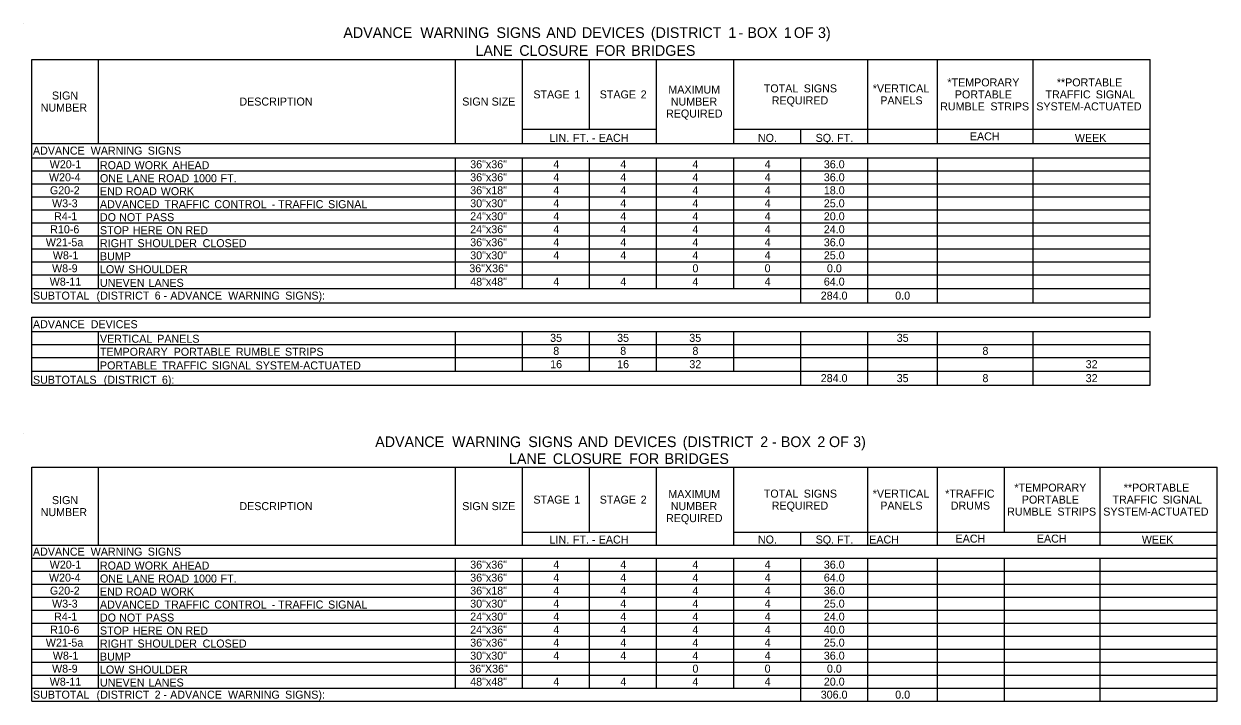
# Model space of a CAD drawing. Extents: x 542596 to 1930787, y -1948294 to 596640.
# Drawn here: x 542596 to 543491, y -1946520 to -1946012 of the extents above; entities that cross this region are included whole.
import ezdxf

# ---------------------------------------------------------------- set-up
doc = ezdxf.new("R2010")
doc.units = 0
doc.layers.add('Default', color=7, linetype='Continuous')

msp = doc.modelspace()

# ---------------------------------------------------------------- linework, layer by layer
at = {"layer": 'Default'}
for p, q in [((542596.4, -1946012.3), (542596.4, -1946012.3)), ((542602.25, -1946039.11), (543440.75, -1946039.11)), ((542602.25, -1946221.43), (542602.25, -1946039.11)), ((542602.25, -1946221.43), (542602.25, -1946039.11)), ((542652.46, -1946102), (542652.46, -1946039.11)), ((542920.1, -1946102), (542920.1, -1946039.11)), ((542970.31, -1946102), (542970.31, -1946039.11)), ((543020.52, -1946091.27), (543020.52, -1946039.11)), ((543070.73, -1946102), (543070.73, -1946039.11)), ((543128.75, -1946102), (543128.75, -1946039.11)), ((543229.17, -1946102), (543229.17, -1946039.11)), ((543281.33, -1946102), (543281.33, -1946039.11)), ((543353, -1946102), (543353, -1946039.11)), ((543440.75, -1946232.16), (543440.75, -1946039.11)), ((542970.31, -1946091.27), (543070.73, -1946091.27)), ((543070.73, -1946102), (543070.73, -1946091.27)), ((543128.75, -1946091.27), (543440.75, -1946091.27)), ((543178.96, -1946102), (543178.96, -1946091.27)), ((543229.17, -1946102), (543229.17, -1946091.27)), ((543281.33, -1946102), (543281.33, -1946091.27)), ((543353, -1946102), (543353, -1946091.27)), ((542602.25, -1946102), (543440.75, -1946102)), ((543070.73, -1946102), (543229.17, -1946102)), ((543229.17, -1946102), (543281.33, -1946102)), ((543281.33, -1946102), (543440.75, -1946102)), ((542602.25, -1946112.72), (543440.75, -1946112.72)), ((542652.46, -1946210.71), (542652.46, -1946112.72)), ((542652.46, -1946210.71), (542652.46, -1946112.72)), ((542920.1, -1946210.71), (542920.1, -1946112.72)), ((542920.1, -1946210.71), (542920.1, -1946112.72)), ((542970.31, -1946210.71), (542970.31, -1946112.72)), ((542970.31, -1946210.71), (542970.31, -1946112.72)), ((543020.52, -1946200.47), (543020.52, -1946112.72)), ((543020.52, -1946210.71), (543020.52, -1946112.72)), ((543070.73, -1946210.71), (543070.73, -1946112.72)), ((543070.73, -1946210.71), (543070.73, -1946112.72)), ((543128.75, -1946210.71), (543128.75, -1946112.72)), ((543178.96, -1946210.71), (543178.96, -1946112.72)), ((543178.96, -1946221.43), (543178.96, -1946112.72)), ((543229.17, -1946200.47), (543229.17, -1946112.72)), ((543229.17, -1946221.43), (543229.17, -1946112.72)), ((543281.33, -1946161.47), (543281.33, -1946112.72)), ((543281.33, -1946221.43), (543281.33, -1946112.72)), ((543353, -1946221.43), (543353, -1946112.72)), ((542602.25, -1946122.47), (543440.75, -1946122.47)), ((542602.25, -1946132.22), (543440.75, -1946132.22)), ((542602.25, -1946141.97), (543440.75, -1946141.97)), ((542602.25, -1946151.72), (543440.75, -1946151.72)), ((542602.25, -1946161.47), (543440.75, -1946161.47)), ((542602.25, -1946171.22), (543440.75, -1946171.22)), ((543281.33, -1946221.43), (543281.33, -1946171.22)), ((542602.25, -1946180.97), (543440.75, -1946180.97)), ((542602.25, -1946190.72), (543440.75, -1946190.72)), ((542602.25, -1946200.47), (543440.75, -1946200.47)), ((542602.25, -1946210.71), (543440.75, -1946210.71)), ((543178.96, -1946210.71), (543440.75, -1946210.71)), ((543353, -1946221.43), (543353, -1946210.71)), ((542602.25, -1946221.43), (543440.75, -1946221.43)), ((543353, -1946221.43), (543440.75, -1946221.43)), ((542602.25, -1946232.16), (543440.75, -1946232.16)), ((542602.25, -1946283.35), (542602.25, -1946232.16)), ((542602.25, -1946283.35), (542602.25, -1946232.16)), ((542652.46, -1946232.16), (543353, -1946232.16)), ((543353, -1946232.16), (543440.75, -1946232.16)), ((542602.25, -1946242.88), (543440.75, -1946242.88)), ((542652.46, -1946272.62), (542652.46, -1946242.88)), ((542652.46, -1946272.62), (542652.46, -1946242.88)), ((542920.1, -1946272.62), (542920.1, -1946242.88)), ((542920.1, -1946272.62), (542920.1, -1946242.88)), ((542970.31, -1946272.62), (542970.31, -1946242.88)), ((542970.31, -1946272.62), (542970.31, -1946242.88)), ((543020.52, -1946272.62), (543020.52, -1946242.88)), ((543020.52, -1946272.62), (543020.52, -1946242.88)), ((543070.73, -1946272.62), (543070.73, -1946242.88)), ((543070.73, -1946272.62), (543070.73, -1946242.88)), ((543128.75, -1946272.62), (543128.75, -1946242.88)), ((543178.96, -1946272.62), (543178.96, -1946242.88)), ((543178.96, -1946283.35), (543178.96, -1946242.88)), ((543229.17, -1946283.35), (543229.17, -1946242.88)), ((543229.17, -1946283.35), (543229.17, -1946242.88)), ((543281.33, -1946283.35), (543281.33, -1946242.88)), ((543281.33, -1946283.35), (543281.33, -1946242.88)), ((543353, -1946283.35), (543353, -1946242.88)), ((543440.75, -1946283.35), (543440.75, -1946242.88)), ((542602.25, -1946252.63), (543440.75, -1946252.63)), ((543353, -1946262.38), (543353, -1946252.63)), ((542602.25, -1946262.38), (543440.75, -1946262.38)), ((542602.25, -1946272.62), (543440.75, -1946272.62)), ((542602.25, -1946272.62), (543440.75, -1946272.62)), ((543353, -1946283.35), (543353, -1946272.62)), ((542602.25, -1946283.35), (543440.75, -1946283.35)), ((542596.4, -1946319.34), (542596.4, -1946319.34)), ((542602.25, -1946344.69), (543490.96, -1946344.69)), ((542602.25, -1946520.19), (542602.25, -1946344.69)), ((542602.25, -1946520.19), (542602.25, -1946344.69)), ((542652.46, -1946403.19), (542652.46, -1946344.69)), ((542920.1, -1946403.19), (542920.1, -1946344.69)), ((542970.31, -1946403.19), (542970.31, -1946344.69)), ((543020.52, -1946393.44), (543020.52, -1946344.69)), ((543070.73, -1946403.19), (543070.73, -1946344.69)), ((543128.75, -1946403.19), (543128.75, -1946344.69)), ((543229.17, -1946403.19), (543229.17, -1946344.69)), ((543281.33, -1946403.19), (543281.33, -1946344.69)), ((543331.55, -1946393.44), (543331.55, -1946344.69)), ((543403.21, -1946403.19), (543403.21, -1946344.69)), ((543490.96, -1946520.19), (543490.96, -1946344.69)), ((542970.31, -1946393.44), (543070.73, -1946393.44)), ((543070.73, -1946403.19), (543070.73, -1946393.44)), ((543128.75, -1946393.44), (543490.96, -1946393.44)), ((543178.96, -1946403.19), (543178.96, -1946393.44)), ((543281.33, -1946403.19), (543281.33, -1946393.44)), ((543403.21, -1946403.19), (543403.21, -1946393.44)), ((542602.25, -1946403.19), (543490.96, -1946403.19)), ((543070.73, -1946403.19), (543490.96, -1946403.19)), ((542602.25, -1946412.94), (543490.96, -1946412.94)), ((542652.46, -1946510.44), (542652.46, -1946412.94)), ((542652.46, -1946510.44), (542652.46, -1946412.94)), ((542920.1, -1946510.44), (542920.1, -1946412.94)), ((542920.1, -1946510.44), (542920.1, -1946412.94)), ((542970.31, -1946510.44), (542970.31, -1946412.94)), ((542970.31, -1946510.44), (542970.31, -1946412.94)), ((543020.52, -1946500.69), (543020.52, -1946412.94)), ((543020.52, -1946510.44), (543020.52, -1946412.94)), ((543070.73, -1946510.44), (543070.73, -1946412.94)), ((543070.73, -1946510.44), (543070.73, -1946412.94)), ((543128.75, -1946510.44), (543128.75, -1946412.94)), ((543178.96, -1946510.44), (543178.96, -1946412.94)), ((543178.96, -1946520.19), (543178.96, -1946412.94)), ((543229.17, -1946520.19), (543229.17, -1946412.94)), ((543229.17, -1946520.19), (543229.17, -1946412.94)), ((543281.33, -1946520.19), (543281.33, -1946412.94)), ((543281.33, -1946520.19), (543281.33, -1946412.94)), ((543331.55, -1946520.19), (543331.55, -1946412.94)), ((543331.55, -1946520.19), (543331.55, -1946412.94)), ((543403.21, -1946520.19), (543403.21, -1946412.94)), ((542602.25, -1946422.69), (543490.96, -1946422.69)), ((542602.25, -1946432.44), (543490.96, -1946432.44)), ((542602.25, -1946442.19), (543490.96, -1946442.19)), ((542602.25, -1946451.94), (543490.96, -1946451.94)), ((542602.25, -1946461.69), (543490.96, -1946461.69)), ((542602.25, -1946471.44), (543490.96, -1946471.44)), ((542602.25, -1946481.19), (543490.96, -1946481.19)), ((542602.25, -1946490.94), (543490.96, -1946490.94)), ((542602.25, -1946500.69), (543490.96, -1946500.69)), ((542602.25, -1946510.44), (543490.96, -1946510.44)), ((542602.25, -1946510.44), (543178.96, -1946510.44)), ((543281.33, -1946510.44), (543490.96, -1946510.44)), ((543403.21, -1946520.19), (543403.21, -1946510.44)), ((542602.25, -1946520.19), (543490.96, -1946520.19))]:
    msp.add_line(p, q, dxfattribs=at)

# ---------------------------------------------------------------- texts
for s, height, p in [('ADVANCE', 8, (542835.92, -1946022.88)), (' WARNING', 8, (542890.64, -1946022.88)), (' SIGNS', 8, (542947.71, -1946022.88)), (' AND', 8, (542985.05, -1946022.88)), (' DEVICES', 8, (543011.82, -1946022.88)), (' (DISTRICT', 8, (543063.45, -1946022.88)), (' 1', 8, (543121.59, -1946022.88)), (' -', 8, (543129.09, -1946022.88)), (' BOX', 8, (543135.84, -1946022.88)), (' 1', 8, (543163.15, -1946022.88)), (' OF', 8, (543170.66, -1946022.88)), (' 3)', 8, (543188.77, -1946022.88)), ('LANE', 8, (542934.96, -1946036.28)), (' CLOSURE', 8, (542964.84, -1946036.28)), (' FOR', 8, (543022.05, -1946036.28)), (' BRIDGES', 8, (543048.69, -1946036.28)), ('TOTAL', 6, (543151.11, -1946063.69)), (' SIGNS', 6, (543178.8, -1946063.69)), ('*VERTICAL', 6, (543232.79, -1946063.69)), ('*TEMPORARY', 6, (543288.74, -1946059.19)), ('**PORTABLE', 6, (543370.76, -1946059.19)), ('SIGN', 6, (542617.44, -1946069.05)), ('STAGE', 6, (542978.37, -1946068.19)), (' 1', 6, (543006.84, -1946068.19)), ('STAGE', 6, (543028.11, -1946068.19)), (' 2', 6, (543056.58, -1946068.19)), ('MAXIMUM', 6, (543079.55, -1946064.55)), ('REQUIRED', 6, (543157.04, -1946072.69)), ('PANELS', 6, (543238.45, -1946072.69)), ('PORTABLE', 6, (543294.32, -1946068.19)), ('TRAFFIC', 6, (543362.28, -1946068.19)), (' SIGNAL', 6, (543397.71, -1946068.19)), ('NUMBER', 6, (542608.98, -1946078.05)), ('DESCRIPTION', 6, (542757.97, -1946073.55)), ('SIGN', 6, (542925.02, -1946073.55)), (' SIZE', 6, (542944.84, -1946073.55)), ('NUMBER', 6, (543081.36, -1946073.55)), ('RUMBLE', 6, (543283.34, -1946077.19)), (' STRIPS', 6, (543318.79, -1946077.19)), ('SYSTEM-ACTUATED', 6, (543355.39, -1946077.19)), ('REQUIRED', 6, (543077.82, -1946082.55)), ('EACH', 6, (543305.61, -1946099.63)), ('LIN.', 6, (542990.48, -1946100.8)), (' FT.', 6, (543005.74, -1946100.8)), (' -', 6, (543020.06, -1946100.8)), (' EACH', 6, (543025.12, -1946100.8)), ('NO.', 6, (543146.69, -1946100.8)), ('SQ.', 6, (543189.97, -1946100.8)), (' FT.', 6, (543203.84, -1946100.8)), ('WEEK', 6, (543384.3, -1946100.8)), ('ADVANCE', 6, (542603.22, -1946110.36)), (' WARNING', 6, (542644.27, -1946110.36)), (' SIGNS', 6, (542687.07, -1946110.36)), ('W20-1', 6, (542615.78, -1946120.6)), ('ROAD', 6, (542653.43, -1946121.27)), (' WORK', 6, (542677.21, -1946121.27)), (' AHEAD', 6, (542705.6, -1946121.27)), ('36"x36"', 6, (542931.01, -1946120.6)), ('4', 6, (542993.29, -1946120.6)), ('4', 6, (543043.5, -1946120.6)), ('4', 6, (543097.61, -1946120.6)), ('4', 6, (543151.73, -1946120.6)), ('36.0', 6, (543196.11, -1946120.6)), ('W20-4', 6, (542615.22, -1946130.35)), ('ONE', 6, (542653.43, -1946131.02)), (' LANE', 6, (542671.16, -1946131.02)), (' ROAD', 6, (542694.94, -1946131.02)), (' 1000', 6, (542721.04, -1946131.02)), (' FT.', 6, (542741.61, -1946131.02)), ('36"x36"', 6, (542931.01, -1946130.35)), ('4', 6, (542993.29, -1946130.35)), ('4', 6, (543043.5, -1946130.35)), ('4', 6, (543097.61, -1946130.35)), ('4', 6, (543151.73, -1946130.35)), ('36.0', 6, (543196.11, -1946130.35)), ('G20-2', 6, (542615.93, -1946140.1)), ('END', 6, (542653.43, -1946140.77)), (' ROAD', 6, (542670.69, -1946140.77)), (' WORK', 6, (542696.79, -1946140.77)), ('36"x18"', 6, (542931.01, -1946140.1)), ('4', 6, (542993.29, -1946140.1)), ('4', 6, (543043.5, -1946140.1)), ('4', 6, (543097.61, -1946140.1)), ('4', 6, (543151.73, -1946140.1)), ('18.0', 6, (543196.11, -1946140.1)), ('W3-3', 6, (542617.53, -1946149.85)), ('ADVANCED', 6, (542653.43, -1946150.52)), (' TRAFFIC', 6, (542699.58, -1946150.52)), (' CONTROL', 6, (542736.97, -1946150.52)), (' TRAFFIC', 6, (542784.84, -1946150.52)), (' SIGNAL', 6, (542822.23, -1946150.52)), ('30"x30"', 6, (542931.01, -1946149.85)), ('4', 6, (542993.29, -1946149.85)), ('4', 6, (543043.5, -1946149.85)), ('4', 6, (543097.61, -1946149.85)), ('4', 6, (543151.73, -1946149.85)), ('25.0', 6, (543196.11, -1946149.85)), ('R4-1', 6, (542619.04, -1946159.6)), ('DO', 6, (542653.43, -1946160.27)), (' NOT', 6, (542665.64, -1946160.27)), (' PASS', 6, (542685.49, -1946160.27)), (' -', 6, (542779.99, -1946150.52)), ('24"x30"', 6, (542931.01, -1946159.6)), ('4', 6, (542993.29, -1946159.6)), ('4', 6, (543043.5, -1946159.6)), ('4', 6, (543097.61, -1946159.6)), ('4', 6, (543151.73, -1946159.6)), ('20.0', 6, (543196.11, -1946159.6)), ('R10-6', 6, (542616.13, -1946169.35)), ('STOP', 6, (542653.43, -1946170.02)), (' HERE', 6, (542675.9, -1946170.02)), (' ON', 6, (542701.07, -1946170.02)), (' RED', 6, (542715.29, -1946170.02)), ('24"x36"', 6, (542931.01, -1946169.35)), ('4', 6, (542993.29, -1946169.35)), ('4', 6, (543043.5, -1946169.35)), ('4', 6, (543097.61, -1946169.35)), ('4', 6, (543151.73, -1946169.35)), ('24.0', 6, (543196.11, -1946169.35)), ('W21-5a', 6, (542612.86, -1946179.1)), ('RIGHT', 6, (542653.43, -1946179.77)), (' SHOULDER', 6, (542679.35, -1946179.77)), (' CLOSED', 6, (542728.15, -1946179.77)), ('36"x36"', 6, (542931.01, -1946179.1)), ('4', 6, (542993.29, -1946179.1)), ('4', 6, (543043.5, -1946179.1)), ('4', 6, (543097.61, -1946179.1)), ('4', 6, (543151.73, -1946179.1)), ('36.0', 6, (543196.11, -1946179.1)), ('W8-1', 6, (542618.11, -1946188.85)), ('30"x30"', 6, (542931.01, -1946188.85)), ('4', 6, (542993.29, -1946188.85)), ('4', 6, (543043.5, -1946188.85)), ('4', 6, (543097.61, -1946188.85)), ('4', 6, (543151.73, -1946188.85)), ('25.0', 6, (543196.11, -1946188.85)), ('BUMP', 6, (542653.43, -1946189.52)), ('W8-9', 6, (542617.53, -1946198.6)), ('LOW', 6, (542653.43, -1946199.27)), (' SHOULDER', 6, (542672.43, -1946199.27)), ('36"X36"', 6, (542930.31, -1946198.6)), ('0', 6, (543097.61, -1946198.6)), ('0', 6, (543151.72, -1946198.6)), ('0.0', 6, (543198.44, -1946198.6)), ('W8-11', 6, (542615.78, -1946208.59)), ('UNEVEN', 6, (542653.43, -1946209.51)), (' LANES', 6, (542687.69, -1946209.51)), ('48"x48"', 6, (542931.01, -1946208.59)), ('4', 6, (542993.29, -1946208.59)), ('4', 6, (543043.5, -1946208.59)), ('4', 6, (543097.61, -1946208.59)), ('4', 6, (543151.73, -1946208.59)), ('64.0', 6, (543196.11, -1946208.59)), ('SUBTOTAL', 6, (542603.22, -1946219.07)), (' (DISTRICT', 6, (542648.62, -1946219.07)), (' 6', 6, (542692.22, -1946219.07)), (' -', 6, (542698.91, -1946219.07)), (' ADVANCE', 6, (542703.96, -1946219.07)), (' WARNING', 6, (542747.34, -1946219.07)), (' SIGNS):', 6, (542790.14, -1946219.07)), ('284.0', 6, (543193.79, -1946219.07)), ('0.0', 6, (543249.64, -1946219.07)), ('ADVANCE', 6, (542603.22, -1946240.52)), (' DEVICES', 6, (542644.27, -1946240.52)), ('VERTICAL', 6, (542653.43, -1946251.43)), (' PANELS', 6, (542694.14, -1946251.43)), ('35', 6, (542990.92, -1946250.76)), ('35', 6, (543041.14, -1946250.76)), ('35', 6, (543095.25, -1946250.76)), ('35', 6, (543250.76, -1946250.76)), ('8', 6, (542993.27, -1946260.51)), ('8', 6, (543043.48, -1946260.51)), ('8', 6, (543097.6, -1946260.51)), ('8', 6, (543315.02, -1946260.51)), ('TEMPORARY', 6, (542653.43, -1946261.18)), (' PORTABLE', 6, (542706.48, -1946261.18)), (' RUMBLE', 6, (542753.09, -1946261.18)), (' STRIPS', 6, (542789.91, -1946261.18)), ('PORTABLE', 6, (542653.43, -1946271.42)), (' TRAFFIC', 6, (542697.72, -1946271.42)), (' SIGNAL', 6, (542735.11, -1946271.42)), (' SYSTEM-ACTUATED', 6, (542767.89, -1946271.42)), ('16', 6, (542990.95, -1946270.5)), ('16', 6, (543041.16, -1946270.5)), ('32', 6, (543095.3, -1946270.5)), ('32', 6, (543392.43, -1946270.5)), ('SUBTOTALS', 6, (542603.22, -1946282.15)), (' (DISTRICT', 6, (542654.05, -1946282.15)), (' 6):', 6, (542697.65, -1946282.15)), ('284.0', 6, (543193.79, -1946280.98)), ('35', 6, (543250.72, -1946280.98)), ('8', 6, (543315.02, -1946280.98)), ('32', 6, (543392.42, -1946280.98)), ('ADVANCE', 8, (542859.77, -1946329.68)), (' WARNING', 8, (542914.5, -1946329.68)), (' SIGNS', 8, (542971.57, -1946329.68)), (' AND', 8, (543008.91, -1946329.68)), (' DEVICES', 8, (543035.68, -1946329.68)), (' (DISTRICT', 8, (543087.31, -1946329.68)), (' 2', 8, (543145.44, -1946329.68)), (' -', 8, (543154.2, -1946329.68)), (' BOX', 8, (543160.94, -1946329.68)), (' 2', 8, (543188.26, -1946329.68)), (' OF', 8, (543197.02, -1946329.68)), (' 3)', 8, (543215.13, -1946329.68)), ('LANE', 8, (542960.07, -1946342.35)), (' CLOSURE', 8, (542989.95, -1946342.35)), (' FOR', 8, (543047.15, -1946342.35)), (' BRIDGES', 8, (543073.8, -1946342.35)), ('MAXIMUM', 6, (543079.55, -1946367.94)), ('TOTAL', 6, (543151.11, -1946367.56)), (' SIGNS', 6, (543178.8, -1946367.56)), ('*VERTICAL', 6, (543232.79, -1946367.56)), ('*TRAFFIC', 6, (543287.1, -1946367.56)), ('*TEMPORARY', 6, (543338.96, -1946363.06)), ('**PORTABLE', 6, (543420.97, -1946363.06)), ('SIGN', 6, (542617.44, -1946372.44)), ('DESCRIPTION', 6, (542757.97, -1946376.94)), ('SIGN', 6, (542925.02, -1946376.94)), (' SIZE', 6, (542944.84, -1946376.94)), ('STAGE', 6, (542978.37, -1946372.06)), (' 1', 6, (543006.84, -1946372.06)), ('STAGE', 6, (543028.11, -1946372.06)), (' 2', 6, (543056.58, -1946372.06)), ('NUMBER', 6, (543081.36, -1946376.94)), ('REQUIRED', 6, (543157.04, -1946376.56)), ('PANELS', 6, (543238.45, -1946376.56)), ('DRUMS', 6, (543291.28, -1946376.56)), ('PORTABLE', 6, (543344.53, -1946372.06)), ('TRAFFIC', 6, (543412.5, -1946372.06)), (' SIGNAL', 6, (543447.92, -1946372.06)), ('NUMBER', 6, (542608.98, -1946381.44)), ('REQUIRED', 6, (543077.82, -1946385.94)), ('RUMBLE', 6, (543333.56, -1946381.06)), (' STRIPS', 6, (543369, -1946381.06)), ('SYSTEM-ACTUATED', 6, (543405.6, -1946381.06)), ('LIN.', 6, (542990.48, -1946401.99)), (' FT.', 6, (543005.74, -1946401.99)), (' EACH', 6, (543025.12, -1946401.99)), ('NO.', 6, (543146.69, -1946401.99)), ('SQ.', 6, (543189.97, -1946401.99)), (' FT.', 6, (543203.84, -1946401.99)), ('EACH', 6, (543230.15, -1946401.99)), ('EACH', 6, (543294.88, -1946401.31)), ('EACH', 6, (543355.82, -1946401.31)), ('WEEK', 6, (543434.52, -1946401.99)), ('ADVANCE', 6, (542603.22, -1946411.06)), (' WARNING', 6, (542644.27, -1946411.06)), (' SIGNS', 6, (542687.07, -1946411.06)), (' -', 6, (543020.06, -1946401.99)), ('W20-1', 6, (542615.78, -1946420.81)), ('ROAD', 6, (542653.43, -1946421.49)), (' WORK', 6, (542677.21, -1946421.49)), (' AHEAD', 6, (542705.6, -1946421.49)), ('36"x36"', 6, (542931.01, -1946420.81)), ('4', 6, (542993.29, -1946420.81)), ('4', 6, (543043.5, -1946420.81)), ('4', 6, (543097.61, -1946420.81)), ('4', 6, (543151.73, -1946420.81)), ('36.0', 6, (543196.11, -1946420.81)), ('W20-4', 6, (542615.22, -1946430.56)), ('36"x36"', 6, (542931.01, -1946430.56)), ('4', 6, (542993.29, -1946430.56)), ('4', 6, (543043.5, -1946430.56)), ('4', 6, (543097.61, -1946430.56)), ('4', 6, (543151.73, -1946430.56)), ('64.0', 6, (543196.11, -1946430.56)), ('ONE', 6, (542653.43, -1946431.24)), (' LANE', 6, (542671.16, -1946431.24)), (' ROAD', 6, (542694.94, -1946431.24)), (' 1000', 6, (542721.04, -1946431.24)), (' FT.', 6, (542741.61, -1946431.24)), ('G20-2', 6, (542615.93, -1946440.31)), ('END', 6, (542653.43, -1946440.99)), (' ROAD', 6, (542670.69, -1946440.99)), (' WORK', 6, (542696.79, -1946440.99)), ('36"x18"', 6, (542931.01, -1946440.31)), ('4', 6, (542993.29, -1946440.31)), ('4', 6, (543043.5, -1946440.31)), ('4', 6, (543097.61, -1946440.31)), ('4', 6, (543151.73, -1946440.31)), ('36.0', 6, (543196.11, -1946440.31)), ('W3-3', 6, (542617.53, -1946450.06)), ('ADVANCED', 6, (542653.43, -1946450.74)), (' TRAFFIC', 6, (542699.58, -1946450.74)), (' CONTROL', 6, (542736.97, -1946450.74)), (' -', 6, (542779.99, -1946450.74)), (' TRAFFIC', 6, (542784.84, -1946450.74)), (' SIGNAL', 6, (542822.23, -1946450.74)), ('30"x30"', 6, (542931.01, -1946450.06)), ('4', 6, (542993.29, -1946450.06)), ('4', 6, (543043.5, -1946450.06)), ('4', 6, (543097.61, -1946450.06)), ('4', 6, (543151.73, -1946450.06)), ('25.0', 6, (543196.11, -1946450.06)), ('R4-1', 6, (542619.04, -1946459.81)), ('DO', 6, (542653.43, -1946460.49)), (' NOT', 6, (542665.64, -1946460.49)), (' PASS', 6, (542685.49, -1946460.49)), ('24"x30"', 6, (542931.01, -1946459.81)), ('4', 6, (542993.29, -1946459.81)), ('4', 6, (543043.5, -1946459.81)), ('4', 6, (543097.61, -1946459.81)), ('4', 6, (543151.73, -1946459.81)), ('24.0', 6, (543196.11, -1946459.81)), ('R10-6', 6, (542616.13, -1946469.56)), ('STOP', 6, (542653.43, -1946470.24)), (' HERE', 6, (542675.9, -1946470.24)), (' ON', 6, (542701.07, -1946470.24)), (' RED', 6, (542715.29, -1946470.24)), ('24"x36"', 6, (542931.01, -1946469.56)), ('4', 6, (542993.29, -1946469.56)), ('4', 6, (543043.5, -1946469.56)), ('4', 6, (543097.61, -1946469.56)), ('4', 6, (543151.73, -1946469.56)), ('40.0', 6, (543196.11, -1946469.56)), ('W21-5a', 6, (542612.86, -1946479.31)), ('RIGHT', 6, (542653.43, -1946479.99)), (' SHOULDER', 6, (542679.35, -1946479.99)), (' CLOSED', 6, (542728.15, -1946479.99)), ('36"x36"', 6, (542931.01, -1946479.31)), ('4', 6, (542993.29, -1946479.31)), ('4', 6, (543043.5, -1946479.31)), ('4', 6, (543097.61, -1946479.31)), ('4', 6, (543151.73, -1946479.31)), ('25.0', 6, (543196.11, -1946479.31)), ('W8-1', 6, (542618.11, -1946489.06)), ('BUMP', 6, (542653.43, -1946489.74)), ('30"x30"', 6, (542931.01, -1946489.06)), ('4', 6, (542993.29, -1946489.06)), ('4', 6, (543043.5, -1946489.06)), ('4', 6, (543097.61, -1946489.06)), ('4', 6, (543151.73, -1946489.06)), ('36.0', 6, (543196.11, -1946489.06)), ('W8-9', 6, (542617.53, -1946498.81)), ('LOW', 6, (542653.43, -1946499.49)), (' SHOULDER', 6, (542672.43, -1946499.49)), ('36"X36"', 6, (542930.31, -1946498.81)), ('0', 6, (543097.61, -1946498.81)), ('0', 6, (543151.72, -1946498.81)), ('0.0', 6, (543198.44, -1946498.81)), ('W8-11', 6, (542615.78, -1946508.56)), ('UNEVEN', 6, (542653.43, -1946509.24)), (' LANES', 6, (542687.69, -1946509.24)), ('48"x48"', 6, (542931.01, -1946508.56)), ('4', 6, (542993.29, -1946508.56)), ('4', 6, (543043.5, -1946508.56)), ('4', 6, (543097.61, -1946508.56)), ('4', 6, (543151.73, -1946508.56)), ('20.0', 6, (543196.11, -1946508.56)), ('SUBTOTAL', 6, (542603.22, -1946518.31)), (' (DISTRICT', 6, (542648.62, -1946518.31)), (' 2', 6, (542692.22, -1946518.31)), (' ADVANCE', 6, (542703.84, -1946518.31)), (' WARNING', 6, (542747.21, -1946518.31)), (' SIGNS):', 6, (542790.01, -1946518.31)), ('306.0', 6, (543193.79, -1946518.31)), ('0.0', 6, (543249.64, -1946518.31)), (' -', 6, (542698.78, -1946518.31))]:
    msp.add_text(s, height=height, dxfattribs=at).set_placement(p)

doc.saveas('drawing.dxf')
